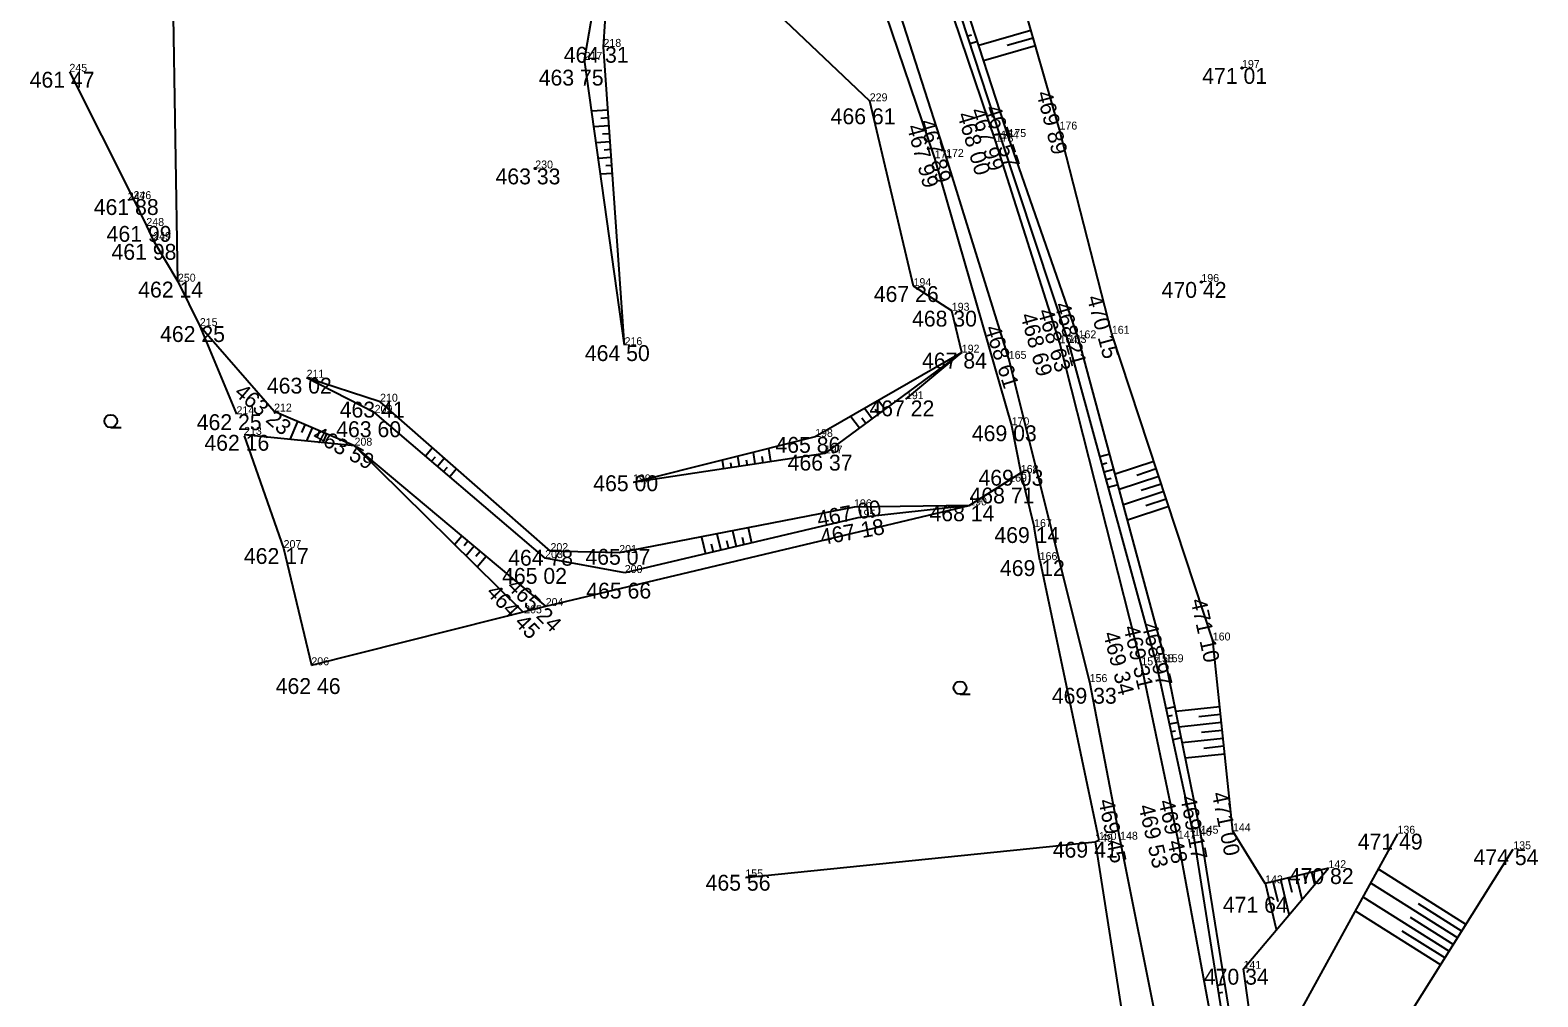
# Model space of a CAD drawing. Extents: x -559180 to -551373, y -1076947 to -1072071.
# Drawn here: x -553645.2 to -553550.2, y -1075375.5 to -1075314.6 of the extents above; entities that cross this region are included whole.
import ezdxf

# ---------------------------------------------------------------- set-up
doc = ezdxf.new("R2010")
doc.units = 0
for name, color, linetype in [('12_PLOTY', 7, 'Continuous'), ('17_KOMUNIKACE', 7, 'Continuous'), ('1_VODA_ZN', 7, 'Continuous'), ('26_SRAFY', 7, 'Continuous'), ('27_HRANA_PATA', 7, 'Continuous'), ('3_BODY', 7, 'Continuous'), ('45_ZN_KULTURY', 7, 'Continuous'), ('6_VYSKY', 7, 'Continuous')]:
    doc.layers.add(name, color=color, linetype=linetype)

# ---------------------------------------------------------------- blocks, each defined once
blk = doc.blocks.new('T')
at = {"layer": '6_VYSKY'}
blk.add_circle((0, 0), 0.05, dxfattribs=at)
blk = doc.blocks.new('POINT_DISPLAY')
blk.add_line((0, 0), (0, 0))
blk = doc.blocks.new('ZAHRAD')
at = {"layer": '45_ZN_KULTURY'}
blk.add_line((0, 0), (0.65, 0.003), dxfattribs=at)
blk.add_circle((0, 0.403), 0.403, dxfattribs=at)

msp = doc.modelspace()

# ---------------------------------------------------------------- linework, layer by layer
at = {"layer": '12_PLOTY'}
for p, q in [((-553635.87, -1075330.41), (-553636.3, -1075304.03)), ((-553593.35, -1075307.4), (-553588.18, -1075322.64)), ((-553642.71, -1075317.19), (-553638.67, -1075325.21)), ((-553588.18, -1075322.64), (-553583.33, -1075339.46)), ((-553638.67, -1075325.21), (-553639.03, -1075325.28)), ((-553638.67, -1075325.21), (-553637.86, -1075326.9)), ((-553637.86, -1075326.9), (-553637.43, -1075327.79)), ((-553637.43, -1075327.79), (-553635.87, -1075330.41)), ((-553635.87, -1075330.41), (-553634.49, -1075333.21)), ((-553634.49, -1075333.21), (-553632.18, -1075338.76)), ((-553583.33, -1075339.46), (-553582.75, -1075342.46)), ((-553631.702, -1075340.116), (-553629.21, -1075347.19)), ((-553586, -1075344.5), (-553582.75, -1075342.46)), ((-553582.75, -1075342.46), (-553581.91, -1075345.87)), ((-553612.69, -1075350.84), (-553586, -1075344.5)), ((-553581.56, -1075347.95), (-553581.91, -1075345.87)), ((-553629.21, -1075347.19), (-553627.46, -1075354.57)), ((-553581.56, -1075347.95), (-553577.83, -1075365.58)), ((-553627.46, -1075354.57), (-553612.69, -1075350.84)), ((-553600.11, -1075367.93), (-553578.07, -1075365.69)), ((-553578.07, -1075365.69), (-553577.83, -1075365.58)), ((-553578.07, -1075365.69), (-553575.67, -1075380.93))]:
    msp.add_line(p, q, dxfattribs=at)
at = {"layer": '17_KOMUNIKACE'}
for p, q in [((-553584.33, -1075321.6), (-553589.42, -1075306.51)), ((-553587.46, -1075322.55), (-553592.34, -1075307.33)), ((-553580.3, -1075334.29), (-553584.33, -1075321.6)), ((-553583.51, -1075335.27), (-553587.46, -1075322.55)), ((-553575.15, -1075354.57), (-553580.3, -1075334.29)), ((-553578.41, -1075355.63), (-553583.51, -1075335.27)), ((-553572.85, -1075365.49), (-553575.15, -1075354.57)), ((-553576.49, -1075365.56), (-553578.41, -1075355.63)), ((-553573.31, -1075381.34), (-553576.49, -1075365.56)), ((-553569.94, -1075381.22), (-553572.85, -1075365.49))]:
    msp.add_line(p, q, dxfattribs=at)
at = {"layer": '26_SRAFY'}
for p, q in [((-553585.867, -1075314.88), (-553586.098, -1075314.956)), ((-553585.403, -1075315.519), (-553582.108, -1075314.572)), ((-553585.481, -1075315.28), (-553585.943, -1075315.431)), ((-553585.095, -1075316.471), (-553581.832, -1075315.533)), ((-553583.61, -1075315.524), (-553581.97, -1075315.053)), ((-553609.79, -1075319.649), (-553608.77, -1075319.577)), ((-553609.651, -1075320.642), (-553608.699, -1075320.575)), ((-553609.227, -1075320.111), (-553608.735, -1075320.076)), ((-553609.511, -1075321.635), (-553608.629, -1075321.572)), ((-553609.123, -1075321.106), (-553608.664, -1075321.073)), ((-553609.018, -1075322.101), (-553608.593, -1075322.071)), ((-553609.372, -1075322.627), (-553608.558, -1075322.57)), ((-553608.913, -1075323.096), (-553608.523, -1075323.068)), ((-553609.233, -1075323.62), (-553608.487, -1075323.567)), ((-553592.581, -1075338.392), (-553592.111, -1075339.03)), ((-553591.926, -1075338.437), (-553591.708, -1075338.734)), ((-553591.708, -1075337.89), (-553591.305, -1075338.438)), ((-553628.794, -1075340.344), (-553628.318, -1075339.223)), ((-553628.065, -1075339.906), (-553627.858, -1075339.418)), ((-553627.751, -1075340.446), (-553627.398, -1075339.613)), ((-553593.453, -1075338.893), (-553592.916, -1075339.623)), ((-553592.765, -1075338.984), (-553592.513, -1075339.327)), ((-553627.083, -1075340.153), (-553626.937, -1075339.808)), ((-553626.708, -1075340.548), (-553626.477, -1075340.003)), ((-553619.818, -1075340.872), (-553620.267, -1075341.399)), ((-553619.664, -1075341.462), (-553619.887, -1075341.723)), ((-553600.595, -1075341.407), (-553600.5, -1075342.043)), ((-553599.621, -1075341.164), (-553599.511, -1075341.894)), ((-553599.075, -1075341.431), (-553599.016, -1075341.82)), ((-553598.646, -1075340.921), (-553598.522, -1075341.745)), ((-553577.144, -1075341.274), (-553577.764, -1075341.444)), ((-553619.066, -1075341.531), (-553619.506, -1075342.047)), ((-553618.908, -1075342.116), (-553619.125, -1075342.371)), ((-553618.314, -1075342.19), (-553618.745, -1075342.696)), ((-553601.57, -1075341.65), (-553601.489, -1075342.192)), ((-553601.038, -1075341.823), (-553600.994, -1075342.117)), ((-553600.057, -1075341.627), (-553600.005, -1075341.968)), ((-553577.323, -1075341.841), (-553577.632, -1075341.926)), ((-553576.883, -1075342.239), (-553577.5, -1075342.408)), ((-553576.809, -1075342.515), (-553574.369, -1075341.712)), ((-553575.446, -1075342.593), (-553574.213, -1075342.187)), ((-553577.061, -1075342.806), (-553577.368, -1075342.891)), ((-553576.623, -1075343.205), (-553577.236, -1075343.373)), ((-553576.548, -1075343.482), (-553574.057, -1075342.662)), ((-553575.159, -1075343.551), (-553573.9, -1075343.137)), ((-553576.288, -1075344.449), (-553573.744, -1075343.612)), ((-553574.872, -1075344.51), (-553573.588, -1075344.087)), ((-553576.027, -1075345.416), (-553573.431, -1075344.561)), ((-553600.919, -1075346.11), (-553600.686, -1075347.095)), ((-553599.937, -1075345.919), (-553599.713, -1075346.864)), ((-553618.438, -1075346.966), (-553617.973, -1075346.412)), ((-553617.835, -1075347.026), (-553617.59, -1075346.733)), ((-553617.724, -1075347.671), (-553617.207, -1075347.054)), ((-553602.884, -1075346.493), (-553602.632, -1075347.556)), ((-553602.269, -1075346.919), (-553602.146, -1075347.441)), ((-553601.902, -1075346.302), (-553601.659, -1075347.326)), ((-553601.292, -1075346.708), (-553601.172, -1075347.21)), ((-553600.314, -1075346.497), (-553600.199, -1075346.98)), ((-553617.095, -1075347.699), (-553616.824, -1075347.375)), ((-553617.01, -1075348.376), (-553616.44, -1075347.696)), ((-553573.038, -1075357.189), (-553573.583, -1075357.308)), ((-553572.983, -1075357.458), (-553570.211, -1075357.165)), ((-553571.521, -1075357.806), (-553570.158, -1075357.662)), ((-553573.207, -1075357.738), (-553573.476, -1075357.796)), ((-553572.838, -1075358.169), (-553573.37, -1075358.285)), ((-553572.782, -1075358.442), (-553570.106, -1075358.159)), ((-553573.001, -1075358.716), (-553573.263, -1075358.773)), ((-553572.639, -1075359.149), (-553573.157, -1075359.262)), ((-553572.582, -1075359.427), (-553570.001, -1075359.154)), ((-553571.368, -1075358.796), (-553570.053, -1075358.657)), ((-553572.381, -1075360.411), (-553569.896, -1075360.148)), ((-553571.215, -1075359.785), (-553569.948, -1075359.651)), ((-553565.828, -1075370.274), (-553566.358, -1075368.071)), ((-553565.649, -1075368.877), (-553565.872, -1075367.954)), ((-553565.027, -1075369.326), (-553565.385, -1075367.837)), ((-553564.763, -1075368.286), (-553564.899, -1075367.72)), ((-553564.227, -1075368.377), (-553564.413, -1075367.603)), ((-553560.233, -1075367.404), (-553554.684, -1075370.892)), ((-553566.628, -1075371.223), (-553567.33, -1075368.305)), ((-553566.536, -1075369.468), (-553566.844, -1075368.188)), ((-553560.716, -1075368.282), (-553555.216, -1075371.738)), ((-553561.199, -1075369.159), (-553555.748, -1075372.585)), ((-553557.712, -1075369.579), (-553554.95, -1075371.315)), ((-553561.682, -1075370.037), (-553556.28, -1075373.432)), ((-553558.22, -1075370.441), (-553555.482, -1075372.162)), ((-553558.727, -1075371.303), (-553556.014, -1075373.009)), ((-553569.884, -1075374.658), (-553570.352, -1075374.732)), ((-553570.039, -1075375.189), (-553570.274, -1075375.226))]:
    msp.add_line(p, q, dxfattribs=at)
at = {"layer": '27_HRANA_PATA'}
for p, q in [((-553610.24, -1075316.44), (-553608.36, -1075305.5)), ((-553609.05, -1075315.62), (-553608.36, -1075305.5)), ((-553592.27, -1075319.05), (-553606.58, -1075305.45)), ((-553583.99, -1075321.4), (-553588.93, -1075306.3)), ((-553583.53, -1075321.3), (-553588.44, -1075306.15)), ((-553580.31, -1075320.83), (-553584.73, -1075305.45)), ((-553607.72, -1075334.41), (-553609.05, -1075315.62)), ((-553607.72, -1075334.41), (-553610.24, -1075316.44)), ((-553589.51, -1075330.69), (-553592.27, -1075319.05)), ((-553579.73, -1075334.27), (-553583.99, -1075321.4)), ((-553579.11, -1075333.98), (-553583.53, -1075321.3)), ((-553577.01, -1075333.69), (-553580.31, -1075320.83)), ((-553587.1, -1075332.24), (-553589.51, -1075330.69)), ((-553586.47, -1075334.88), (-553587.1, -1075332.24)), ((-553629.81, -1075338.59), (-553634.49, -1075333.21)), ((-553570.65, -1075353.01), (-553577.01, -1075333.69)), ((-553574.22, -1075354.38), (-553579.73, -1075334.27)), ((-553573.61, -1075354.38), (-553579.11, -1075333.98)), ((-553586.47, -1075334.88), (-553595.71, -1075340.19)), ((-553586.47, -1075334.88), (-553595.1, -1075341.23)), ((-553589.99, -1075337.81), (-553586.47, -1075334.88)), ((-553623.47, -1075338.67), (-553627.76, -1075336.46)), ((-553623.13, -1075337.97), (-553627.76, -1075336.46)), ((-553624.74, -1075340.74), (-553629.81, -1075338.59)), ((-553612.73, -1075347.82), (-553623.47, -1075338.67)), ((-553612.39, -1075347.38), (-553623.13, -1075337.97)), ((-553624.74, -1075340.74), (-553631.7, -1075340.06)), ((-553595.71, -1075340.19), (-553607.19, -1075343.05)), ((-553612.69, -1075350.84), (-553624.74, -1075340.74)), ((-553614.144, -1075351.207), (-553624.74, -1075340.74)), ((-553595.1, -1075341.23), (-553607.19, -1075343.05)), ((-553593.26, -1075344.62), (-553608.06, -1075347.5)), ((-553593.03, -1075345.28), (-553607.71, -1075348.76)), ((-553586, -1075344.5), (-553593.26, -1075344.62)), ((-553586, -1075344.5), (-553593.03, -1075345.28)), ((-553607.71, -1075348.76), (-553612.73, -1075347.82)), ((-553608.06, -1075347.5), (-553612.39, -1075347.38)), ((-553569.38, -1075365.03), (-553570.65, -1075353.01)), ((-553571.84, -1075365.31), (-553574.22, -1075354.38)), ((-553571.41, -1075365.18), (-553573.61, -1075354.38)), ((-553568.83, -1075381.2), (-553571.41, -1075365.18)), ((-553567.35, -1075368.31), (-553569.38, -1075365.03)), ((-553559.01, -1075365.18), (-553567.69, -1075380.96)), ((-553569.37, -1075380.95), (-553571.84, -1075365.31)), ((-553558.12, -1075376.36), (-553551.71, -1075366.16)), ((-553568.71, -1075373.69), (-553563.36, -1075367.35)), ((-553563.36, -1075367.35), (-553567.35, -1075368.31)), ((-553567.69, -1075380.96), (-553568.71, -1075373.69))]:
    msp.add_line(p, q, dxfattribs=at)

# ---------------------------------------------------------------- block references
at = {"layer": '12_PLOTY'}
msp.add_blockref('POINT_DISPLAY', (-553632.18, -1075338.76), dxfattribs=at)
at = {"layer": '1_VODA_ZN'}
for p in [(-553609.05, -1075315.62), (-553610.24, -1075316.44), (-553642.71, -1075317.19), (-553568.81, -1075316.95), (-553592.27, -1075319.05), (-553583.99, -1075321.4), (-553583.53, -1075321.3), (-553580.31, -1075320.83), (-553584.33, -1075321.6), (-553613.35, -1075323.28), (-553588.18, -1075322.64), (-553587.46, -1075322.55), (-553639.03, -1075325.28), (-553638.67, -1075325.21), (-553637.86, -1075326.9), (-553637.43, -1075327.79), (-553635.87, -1075330.41), (-553589.51, -1075330.69), (-553571.37, -1075330.43), (-553587.1, -1075332.24), (-553634.49, -1075333.21), (-553577.01, -1075333.69), (-553607.72, -1075334.41), (-553580.3, -1075334.29), (-553579.73, -1075334.27), (-553579.11, -1075333.98), (-553586.47, -1075334.88), (-553583.51, -1075335.27), (-553627.76, -1075336.46), (-553629.81, -1075338.59), (-553623.47, -1075338.67), (-553623.13, -1075337.97), (-553589.99, -1075337.81), (-553632.18, -1075338.76), (-553583.33, -1075339.46), (-553631.7, -1075340.06), (-553595.71, -1075340.19), (-553624.74, -1075340.74), (-553595.1, -1075341.23), (-553582.75, -1075342.46), (-553607.19, -1075343.05), (-553583.48, -1075343.01), (-553593.26, -1075344.62), (-553593.03, -1075345.28), (-553586, -1075344.5), (-553581.91, -1075345.87), (-553629.21, -1075347.19), (-553612.73, -1075347.82), (-553612.39, -1075347.38), (-553608.06, -1075347.5), (-553581.56, -1075347.95), (-553607.71, -1075348.76), (-553612.69, -1075350.84), (-553614.05, -1075351.3), (-553570.65, -1075353.01), (-553627.46, -1075354.57), (-553575.15, -1075354.57), (-553574.22, -1075354.38), (-553573.61, -1075354.38), (-553578.41, -1075355.63), (-553571.41, -1075365.18), (-553569.38, -1075365.03), (-553559.01, -1075365.18), (-553578.07, -1075365.69), (-553577.83, -1075365.58), (-553576.49, -1075365.56), (-553572.85, -1075365.49), (-553571.84, -1075365.31), (-553551.71, -1075366.16), (-553600.11, -1075367.93), (-553563.36, -1075367.35), (-553567.35, -1075368.31), (-553568.71, -1075373.69)]:
    msp.add_blockref('POINT_DISPLAY', p, dxfattribs=at)
at = {"layer": '45_ZN_KULTURY'}
for p in [(-553640.101, -1075339.597), (-553586.582, -1075356.394)]:
    msp.add_blockref('ZAHRAD', p, dxfattribs=at)
at = {"layer": '6_VYSKY'}
for p in [(-553568.81, -1075316.95), (-553568.81, -1075316.95), (-553613.35, -1075323.28), (-553613.35, -1075323.28), (-553571.37, -1075330.43), (-553571.37, -1075330.43)]:
    msp.add_blockref('T', p, dxfattribs=at)

# ---------------------------------------------------------------- texts
at = {"layer": '3_BODY'}
for s, p in [('218', (-553609.05, -1075315.62)), ('245', (-553642.71, -1075317.19)), ('217', (-553610.24, -1075316.44)), ('197', (-553568.81, -1075316.95)), ('229', (-553592.27, -1075319.05)), ('176', (-553580.31, -1075320.83)), ('173', (-553584.33, -1075321.6)), ('174', (-553583.99, -1075321.4)), ('175', (-553583.53, -1075321.3)), ('171', (-553588.18, -1075322.64)), ('172', (-553587.46, -1075322.55)), ('230', (-553613.35, -1075323.28)), ('247', (-553639.03, -1075325.28)), ('246', (-553638.67, -1075325.21)), ('248', (-553637.86, -1075326.9)), ('249', (-553637.43, -1075327.79)), ('250', (-553635.87, -1075330.41)), ('196', (-553571.37, -1075330.43)), ('194', (-553589.51, -1075330.69)), ('193', (-553587.1, -1075332.24)), ('215', (-553634.49, -1075333.21)), ('216', (-553607.72, -1075334.41)), ('164', (-553580.3, -1075334.29)), ('163', (-553579.73, -1075334.27)), ('162', (-553579.11, -1075333.98)), ('161', (-553577.01, -1075333.69)), ('192', (-553586.47, -1075334.88)), ('165', (-553583.51, -1075335.27)), ('211', (-553627.76, -1075336.46)), ('210', (-553623.13, -1075337.97)), ('191', (-553589.99, -1075337.81)), ('214', (-553632.18, -1075338.76)), ('212', (-553629.81, -1075338.59)), ('209', (-553623.47, -1075338.67)), ('213', (-553631.7, -1075340.06)), ('170', (-553583.33, -1075339.46)), ('208', (-553624.74, -1075340.74)), ('198', (-553595.71, -1075340.19)), ('197', (-553595.1, -1075341.23)), ('168', (-553582.75, -1075342.46)), ('199', (-553607.19, -1075343.05)), ('169', (-553583.48, -1075343.01)), ('196', (-553593.26, -1075344.62)), ('190', (-553586, -1075344.5)), ('195', (-553593.03, -1075345.28)), ('167', (-553581.91, -1075345.87)), ('207', (-553629.21, -1075347.19)), ('202', (-553612.39, -1075347.38)), ('201', (-553608.06, -1075347.5)), ('203', (-553612.73, -1075347.82)), ('166', (-553581.56, -1075347.95)), ('200', (-553607.71, -1075348.76)), ('205', (-553614.05, -1075351.3)), ('204', (-553612.69, -1075350.84)), ('160', (-553570.65, -1075353.01)), ('158', (-553574.22, -1075354.38)), ('159', (-553573.61, -1075354.38)), ('206', (-553627.46, -1075354.57)), ('157', (-553575.15, -1075354.57)), ('156', (-553578.41, -1075355.63)), ('149', (-553578.07, -1075365.69)), ('150', (-553577.83, -1075365.58)), ('148', (-553576.49, -1075365.56)), ('147', (-553572.85, -1075365.49)), ('146', (-553571.84, -1075365.31)), ('145', (-553571.41, -1075365.18)), ('144', (-553569.38, -1075365.03)), ('136', (-553559.01, -1075365.18)), ('135', (-553551.71, -1075366.16)), ('142', (-553563.36, -1075367.35)), ('155', (-553600.11, -1075367.93)), ('143', (-553567.35, -1075368.31)), ('141', (-553568.71, -1075373.69))]:
    msp.add_text(s, height=0.5, dxfattribs=at).set_placement(p)
at = {"layer": '6_VYSKY'}
for s, p in [('464 31', (-553611.555, -1075316.62)), ('461 47', (-553645.215, -1075318.19)), ('463 75', (-553613.132, -1075318.059)), ('471 01', (-553571.315, -1075317.95)), ('466 61', (-553594.734, -1075320.494)), ('463 33', (-553615.855, -1075324.28)), ('461 88', (-553641.175, -1075326.21)), ('461 99', (-553640.365, -1075327.9)), ('461 98', (-553640.056, -1075329.033)), ('462 14', (-553638.375, -1075331.41)), ('467 26', (-553592.015, -1075331.69)), ('470 42', (-553573.875, -1075331.43)), ('468 30', (-553589.605, -1075333.24)), ('462 25', (-553636.995, -1075334.21)), ('464 50', (-553610.225, -1075335.41)), ('467 84', (-553588.975, -1075335.88)), ('463 02', (-553630.265, -1075337.46)), ('463 41', (-553625.675, -1075338.97)), ('467 22', (-553592.293, -1075338.89)), ('462 25', (-553634.685, -1075339.76)), ('463 60', (-553625.897, -1075340.203)), ('469 03', (-553585.835, -1075340.46)), ('462 16', (-553634.205, -1075341.06)), ('465 86', (-553598.215, -1075341.19)), ('466 37', (-553597.444, -1075342.311)), ('469 03', (-553585.417, -1075343.259)), ('465 00', (-553609.695, -1075343.606)), ('468 71', (-553585.985, -1075344.38)), ('468 14', (-553588.505, -1075345.5)), ('469 14', (-553584.415, -1075346.87)), ('462 17', (-553631.715, -1075348.19)), ('465 07', (-553610.189, -1075348.24)), ('464 78', (-553615.057, -1075348.299)), ('469 12', (-553584.065, -1075348.95)), ('465 02', (-553615.44, -1075349.443)), ('465 66', (-553610.135, -1075350.37)), ('462 46', (-553629.709, -1075356.381)), ('469 33', (-553580.794, -1075356.993)), ('471 49', (-553561.515, -1075366.18)), ('469 41', (-553580.737, -1075366.69)), ('474 54', (-553554.215, -1075367.16)), ('465 56', (-553602.615, -1075368.769)), ('470 82', (-553565.865, -1075368.35)), ('471 64', (-553570.017, -1075370.157)), ('470 34', (-553571.215, -1075374.69))]:
    msp.add_text(s, height=1, dxfattribs=at).set_placement(p)
for s, rotation, p in [('469 89', 284.48687, (-553581.773, -1075318.533)), ('467 99', 287.77911, (-553585.954, -1075319.637)), ('467 57', 288.32667, (-553585.013, -1075319.48)), ('467 99', 285.29402, (-553589.942, -1075320.646)), ('467 89', 285.71984, (-553589.157, -1075320.339)), ('468 00', 286.78753, (-553586.77, -1075319.886)), ('468 21', 285.52891, (-553580.634, -1075331.86)), ('470 15', 285.27046, (-553578.6, -1075331.407)), ('468 69', 285.65036, (-553582.79, -1075332.529)), ('468 63', 286.52801, (-553581.693, -1075332.272)), ('468 61', 287.63572, (-553585.029, -1075333.328)), ('463 23', 319.49539, (-553632.38, -1075337.498)), ('463 59', 331.43778, (-553627.459, -1075340.335)), ('467 00', 10.50483, (-553595.493, -1075345.862)), ('467 18', 9.91038, (-553595.305, -1075347.006)), ('464 45', 313.25284, (-553616.497, -1075350.034)), ('465 24', 314.98882, (-553615.192, -1075349.679)), ('471 10', 282.4933, (-553572.057, -1075350.484)), ('468 97', 284.16539, (-553575.144, -1075352.013)), ('469 34', 284.42323, (-553577.57, -1075352.576)), ('469 31', 283.36022, (-553576.289, -1075352.184)), ('469 45', 281.47499, (-553577.865, -1075363.099)), ('469 48', 282.43278, (-553574.076, -1075363.147)), ('469 17', 280.4462, (-553572.7, -1075362.87)), ('471 00', 281.72931, (-553570.723, -1075362.648)), ('469 53', 283.19987, (-553575.342, -1075363.455))]:
    msp.add_text(s, height=1, rotation=rotation, dxfattribs=at).set_placement(p)

doc.saveas('drawing.dxf')
